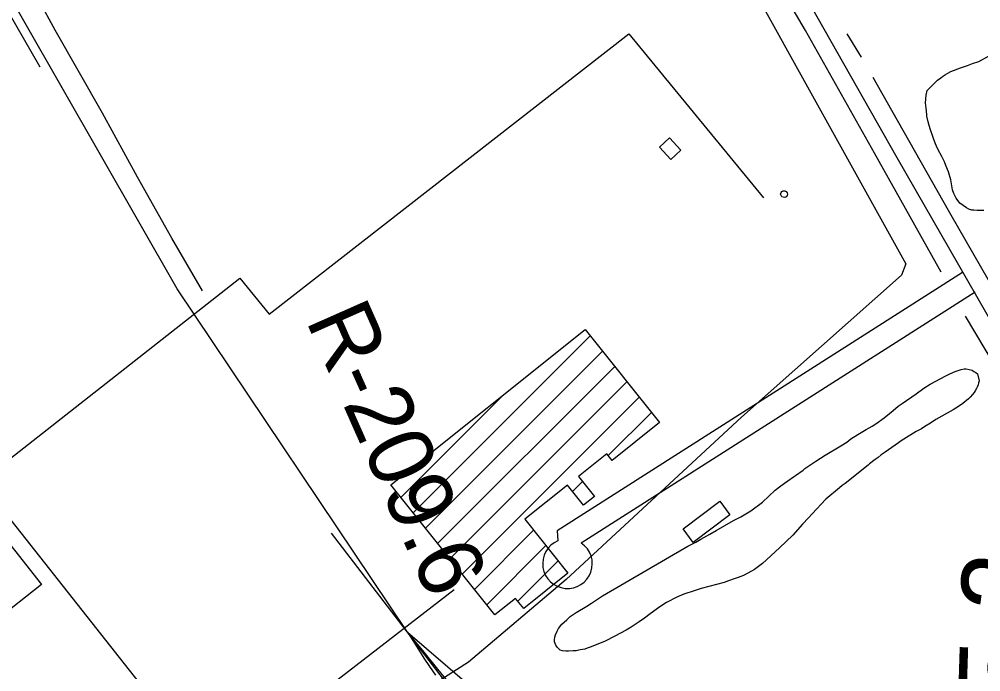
# Model space of a CAD drawing. Extents: x 3297753 to 3335611, y 652252 to 677623.
# Drawn here: x 3314328 to 3315560, y 661323 to 662159 of the extents above; entities that cross this region are included whole.
import ezdxf

# ---------------------------------------------------------------- set-up
doc = ezdxf.new("R2010")
doc.units = 0
for name, color, linetype in [('V-BLDG-OTLN', 7, 'Continuous'), ('V-DOMW-TANK', 7, 'Continuous'), ('V-RAIL-TRAK', 7, 'Continuous'), ('V-RIVR-EDGE', 7, 'Continuous'), ('V-RIVR-RANG-IDEN', 7, 'Continuous'), ('V-ROAD-CNTR', 7, 'Continuous'), ('V-SITE-OTLN', 7, 'Continuous'), ('V-SITE-VEGE', 7, 'Continuous'), ('V-SURV-IDEN', 7, 'Continuous'), ('V-TOPO-SHOR', 7, 'Continuous'), ('V-UTIL-LINE', 7, 'Continuous')]:
    doc.layers.add(name, color=color, linetype=linetype)

msp = doc.modelspace()

# ---------------------------------------------------------------- linework, layer by layer
at = {"layer": 'V-BLDG-OTLN'}
for p, q in [((3314832.2, 661526.9), (3315059.1, 661753.7)), ((3314847.9, 661507.2), (3315074.8, 661734.1)), ((3314863.6, 661487.6), (3315090.5, 661714.4)), ((3314879.3, 661467.9), (3315106.2, 661694.8)), ((3314816.5, 661546.5), (3314947.4, 661677.5)), ((3314895, 661448.3), (3315121.9, 661675.1)), ((3315082.3, 661600.2), (3315137.6, 661655.5)), ((3315036.3, 661554.2), (3315049.2, 661567.1)), ((3314910.8, 661428.6), (3314986.5, 661504.4)), ((3314926.5, 661409), (3315002.2, 661484.7)), ((3314966.4, 661413.6), (3315017.9, 661465.1))]:
    msp.add_line(p, q, dxfattribs=at)
for points in [[(3315160.6, 662007.2), (3315175.3, 661991.6), (3315162.6, 661979.6), (3315147.9, 661995.2)], [(3314803.7, 661562.6), (3315052.8, 661761.6), (3315148.1, 661642.4), (3315087.4, 661593.9), (3315080.6, 661602.5), (3315044.1, 661573.3), (3315064.5, 661547.9), (3315050.4, 661536.6), (3315029.9, 661562.2), (3314975.2, 661518.5), (3315030.5, 661449.4), (3314973.9, 661404.2), (3314963.5, 661417.1), (3314936.8, 661396)], [(3315178.1, 661506.3), (3315225.1, 661541.5), (3315238.1, 661524.1), (3315191.1, 661488.9)], [(3314167.4, 661429.1), (3314286.4, 661522.9), (3314355.9, 661434.8), (3314237, 661341)]]:
    msp.add_lwpolyline(points, close=True, dxfattribs=at)
at = {"layer": 'V-DOMW-TANK'}
msp.add_lwpolyline([(3315311.8, 661935.2), (3315311.4, 661933.5), (3315310.2, 661931.9), (3315308.3, 661931), (3315306.3, 661931.1), (3315304.8, 661931.8), (3315303.6, 661933.2), (3315303.1, 661935.2), (3315303.6, 661937.3), (3315304.8, 661938.7), (3315306.3, 661939.4), (3315308.3, 661939.5), (3315310.2, 661938.6), (3315311.4, 661937)], close=True, dxfattribs=at)
at = {"layer": 'V-RAIL-TRAK'}
for points in [[(3314883.7, 661302.6), (3314864, 661326.4), (3314844.6, 661350.3), (3314825.2, 661374), (3314530.1, 661813.9), (3314234.9, 662329.3)], [(3314825.2, 661374), (3314832, 661363.1), (3314839, 661351.8), (3314846.1, 661340.7), (3314853.3, 661329.7), (3314860.8, 661318.8)], [(3314825.2, 661374), (3314901.1, 661308.4), (3314941.6, 661279), (3314978.9, 661251.9), (3314988.1, 661243.5), (3314997.1, 661234.9), (3315006, 661226.2), (3315014.7, 661217.3), (3315023.2, 661208.2), (3315031.6, 661199), (3315039.8, 661189.7), (3315047.9, 661180.2), (3315175.9, 661016.4)]]:
    msp.add_lwpolyline(points, dxfattribs=at)
at = {"layer": 'V-RIVR-EDGE'}
msp.add_spline([(3319472.9, 662096.8), (3319451.4, 662084.8), (3319431.4, 662073.3), (3319412.8, 662065.4), (3319386.6, 662059.7), (3319355.1, 662056.1), (3319321.5, 662047.4), (3319286.7, 662035.9), (3319261.8, 662024.4), (3319253.9, 662022.3), (3319244, 662022.3), (3319236.9, 662020.3), (3319220.3, 662007.1), (3319214.1, 661999.2), (3319197.9, 661992.6), (3319174.7, 661985.2), (3319135.2, 661974.5), (3319095.8, 661962.6), (3319061.8, 661950.7), (3319035.7, 661940.8), (3319017, 661932.5), (3319004.2, 661925.1), (3318977.6, 661914.4), (3318949.4, 661908.7), (3318929.1, 661903.3), (3318893.4, 661894.3), (3318836.2, 661878.7), (3318802.2, 661869.7), (3318784.3, 661864.3), (3318761.1, 661859.4), (3318735.4, 661848.3), (3318707.2, 661836.3), (3318683.9, 661831.8), (3318667.8, 661829.8), (3318647.9, 661824.9), (3318612.2, 661812.5), (3318583.6, 661801.4), (3318550.8, 661789.5), (3318517.2, 661780.8), (3318486.9, 661770.5), (3318459.1, 661757.8), (3318437.1, 661748.7), (3318401.1, 661732.6), (3318376.3, 661719.7), (3318350.3, 661712.4), (3318322.7, 661702.9), (3318295.6, 661690.6), (3318275.9, 661686.7), (3318257.8, 661681.1), (3318243.7, 661673.2), (3318214.4, 661661.5), (3318180.6, 661645.8), (3318148.4, 661630.1), (3318131.5, 661619.4), (3318111.1, 661604.8), (3318079.5, 661575), (3318056.4, 661560.4), (3318032.7, 661542.4), (3318016.3, 661532.3), (3317961.5, 661489.7), (3317862.7, 661415.5), (3317830, 661391.9), (3317829.4, 661388.6), (3317827.2, 661382.9), (3317810.8, 661375.6), (3317786, 661359.9), (3317761.1, 661342.5), (3317743.6, 661322.8), (3317726.1, 661300.9), (3317708.6, 661279), (3317696.7, 661270.6), (3317673.6, 661255.4), (3317601.3, 661201.5), (3317560.7, 661171.7), (3317529.1, 661153.2), (3317513.8, 661140.3), (3317483.9, 661117.2), (3317464.2, 661105.5), (3317423.5, 661083), (3317409.4, 661079.1), (3317401.5, 661079.1), (3317375, 661065.7), (3317364.3, 661058.9), (3317348.5, 661051.1), (3317330.5, 661046.6), (3317307.3, 661033.2), (3317289.3, 661024.8), (3317263.9, 661012.4), (3317240.8, 661008.5), (3317230.1, 661004), (3317228.4, 661000.1), (3317221.6, 660998.4), (3317196.2, 660991.2), (3317170.3, 660981.7), (3317149.4, 660978.3), (3317103.2, 660961), (3317073.3, 660949.8), (3317034.3, 660929.6), (3316996, 660910), (3316948, 660887), (3316914.7, 660873.5), (3316886, 660860.6), (3316880.9, 660856.2), (3316871.3, 660848.3), (3316865.7, 660846.6), (3316855.5, 660846.6), (3316850.4, 660846.6), (3316844.2, 660840.5), (3316839.7, 660839.9), (3316835.8, 660840.5), (3316830.7, 660836.6), (3316818.8, 660828.7), (3316813.8, 660828.1), (3316808.1, 660827), (3316803.6, 660827), (3316796.8, 660818.6), (3316785, 660809.6), (3316774.8, 660802.9), (3316771.4, 660796.1), (3316765.2, 660779.2), (3316755.6, 660759.5), (3316745.9, 660744.3), (3316732.4, 660728.6), (3316712.6, 660717.9), (3316683.9, 660703.4), (3316676.5, 660701.1), (3316664.7, 660695.5), (3316651.7, 660680.3), (3316633, 660666.9), (3316616.1, 660656.2), (3316590.1, 660637.1), (3316544.4, 660603.4), (3316510, 660581), (3316472.7, 660551.7), (3316428.7, 660523.1), (3316390.3, 660495.6), (3316363.8, 660477.6), (3316349.7, 660469.8), (3316341.2, 660464.7), (3316335, 660464.7), (3316325.4, 660464.8), (3316313.6, 660461.4), (3316289.9, 660457), (3316257.2, 660443.5), (3316237.5, 660436.3), (3316207, 660423.9), (3316177.1, 660405.4), (3316154.5, 660393.1), (3316131.9, 660375.1), (3316110.5, 660362.2), (3316095.3, 660353.2), (3316080, 660338), (3316051.2, 660312.7), (3316013.9, 660270.6), (3315988.5, 660245.8), (3315960.3, 660217.2), (3315939.9, 660200.9), (3315925.8, 660185.1), (3315911.1, 660173.9), (3315895.3, 660159.9), (3315882.9, 660145.8), (3315867.6, 660130.1), (3315849, 660120), (3315837.7, 660109.3), (3315808.9, 660080.1), (3315786.9, 660062.1), (3315758.1, 660038.5), (3315733.8, 660018.8), (3315725.3, 660002.5), (3315692, 659976.7), (3315659.8, 659949.1), (3315603.4, 659904.2), (3315571.2, 659873.3), (3315569.5, 659873.3), (3315558.8, 659868.8), (3315547.5, 659863.2), (3315527.7, 659844.1), (3315506.3, 659828.4), (3315477.5, 659812.1), (3315461.1, 659805.9), (3315440.8, 659793.6), (3315429.5, 659781.8), (3315402.4, 659758.2), (3315361.8, 659731.8), (3315304.2, 659696.4), (3315255.7, 659666.7), (3315169.9, 659624.7), (3315140, 659611.8), (3315123.7, 659603.4), (3315098.8, 659588.8), (3315044.6, 659551.1), (3314989.9, 659507.3), (3314954.3, 659474.7), (3314934, 659462.4), (3314926.1, 659452.8), (3314915.9, 659440.5), (3314897.8, 659423.6), (3314866.8, 659396.1), (3314844.7, 659376.4), (3314848.7, 659370.7), (3314825, 659355), (3314801.8, 659342.7), (3314762.3, 659320.8), (3314730.2, 659303.4), (3314711, 659290.5), (3314664.7, 659256.3), (3314628.6, 659235.5), (3314603.2, 659218.1), (3314584.5, 659209.7), (3314564.8, 659208), (3314555.8, 659204.7), (3314546.8, 659196.2), (3314528.1, 659174.9), (3314492.5, 659118.6), (3314473.8, 659095), (3314450.7, 659074.8), (3314428.7, 659060.2), (3314423, 659054.6), (3314416.2, 659044.4), (3314398.1, 659027.6), (3314375.6, 659007.9), (3314366.5, 659005.1), (3314353.6, 659002.3), (3314347.4, 658997.3), (3314346.8, 658988.8), (3314351.3, 658983.2), (3314350.7, 658974.2), (3314342.8, 658961.8), (3314329.2, 658955.1), (3314311.7, 658940.4), (3314310, 658930.3), (3314294.2, 658921.9), (3314283.5, 658914.6), (3314276.1, 658903.9), (3314272.7, 658896), (3314237.7, 658871.3), (3314206.7, 658853.4), (3314198.2, 658851.1), (3314192, 658850.6), (3314180.2, 658846.1), (3314172.3, 658836.5), (3314164.4, 658823.6), (3314142.3, 658810.1), (3314120.9, 658792.7), (3314097.2, 658778.7), (3314086.5, 658769.1), (3314082.5, 658762.9), (3314080.2, 658754.5), (3314072.3, 658750), (3314036.8, 658734.3), (3314006.3, 658722), (3313997.3, 658716.4), (3313939.7, 658673.7), (3313888.3, 658635), (3313863.5, 658615.3), (3313820.6, 658586.7), (3313772.6, 658558), (3313732, 658532.8), (3313718.5, 658524.4), (3313711.1, 658521.6), (3313702.7, 658521.6), (3313693.1, 658518.8), (3313674.5, 658511.5), (3313646.8, 658494.7), (3313626.5, 658479), (3313619.7, 658475), (3313610.1, 658464.3), (3313605, 658449.1), (3313597.1, 658444.7), (3313577.9, 658428.9), (3313554.8, 658407.6), (3313537.8, 658387.3), (3313525.4, 658364.2), (3313506.1, 658331.6), (3313489.7, 658309.7)], degree=3, dxfattribs=at)
at = {"layer": 'V-ROAD-CNTR'}
for points in [[(3315691.2, 661565.9), (3315452.6, 661981.7), (3315265.5, 662311.8), (3315068.2, 662658.1), (3314991.7, 662786.7), (3314881.6, 662982.8), (3314817.7, 663095.5), (3314653, 663387.7)], [(3315536.1, 661834.9), (3315016.7, 661503.8), (3315017.5, 661490.9)], [(3315552.2, 661809.6), (3315047.7, 661488)], [(3314727.3, 661500.8), (3314914.1, 661256.8), (3315217.7, 660882.3)]]:
    msp.add_lwpolyline(points, dxfattribs=at)
msp.add_arc((3315030, 661461.6), 31.8, 113.0672, 56.0914, dxfattribs=at)
at = {"layer": 'V-SITE-OTLN'}
msp.add_lwpolyline([(3314238.5, 662553.8), (3314592.2, 662807.3), (3314843.4, 662969.8), (3315149.1, 662412.1), (3315463.5, 661846), (3315457.9, 661831.5), (3315253.1, 661649.5), (3315028.5, 661441.3), (3314903.2, 661335.6), (3314820.4, 661282.4), (3315089.4, 660856.8), (3315209.9, 660653.4), (3314859, 660457.6), (3314738.9, 660375), (3314609.1, 660523.7), (3314566.5, 660483.4), (3314505.2, 660440.7), (3314559.6, 660352.4), (3314127.8, 660037.1)], dxfattribs=at)
at = {"layer": 'V-SITE-VEGE'}
for points in [[(3315563.4, 661914), (3315554.8, 661914.1), (3315550.8, 661914.8), (3315548.1, 661914.8), (3315544.2, 661916), (3315541.4, 661917.6), (3315532.8, 661923.5), (3315528.1, 661929.8), (3315525, 661936.1), (3315523.4, 661940.8), (3315521.9, 661948.3), (3315521.1, 661953.4), (3315518, 661963.6), (3315514.8, 661971.8), (3315512.9, 661976.5), (3315509.7, 661983.2), (3315505, 661991.9), (3315502.7, 661996.6), (3315501.5, 661999.7), (3315499.2, 662005.2), (3315498, 662008.8), (3315494.9, 662017.4), (3315493.3, 662022.9), (3315492.1, 662027.6), (3315490.6, 662035.1), (3315490.6, 662037.4), (3315489.4, 662045.3), (3315488.6, 662052.3), (3315489.4, 662061.8), (3315491, 662068), (3315504, 662081), (3315508.3, 662084.1), (3315510.3, 662086.1), (3315514.2, 662088.4), (3315517.4, 662090), (3315521.3, 662092.3), (3315533.5, 662097), (3315542.5, 662100.2), (3315548.8, 662102.5), (3315557, 662105.2), (3315569.6, 662111.9)], [(3315555.4, 661704.8), (3315557.5, 661696), (3315556.6, 661693.4), (3315556, 661690.8), (3315555, 661687.9), (3315554.1, 661685.9), (3315552.2, 661683.3), (3315551.2, 661681), (3315549, 661678.4), (3315545.8, 661675.1), (3315543.9, 661672.8), (3315536.5, 661666.8), (3315531.1, 661663.2), (3315524.3, 661658.8), (3315501.8, 661646.2), (3315495, 661641.8), (3315488, 661637.5), (3315483.5, 661634.5), (3315476.7, 661630.9), (3315457.4, 661619.2), (3315454.2, 661616.6), (3315437.2, 661604.6), (3315431.7, 661601), (3315427.9, 661597.7), (3315424, 661595), (3315417, 661589.4), (3315415.4, 661587.7), (3315415.1, 661588), (3315385.9, 661564.2), (3315382, 661561.6), (3315378.5, 661558.9), (3315361.2, 661544.1), (3315343.3, 661525.6), (3315338.9, 661520.3), (3315331.2, 661512.1), (3315318.8, 661498.3), (3315301.8, 661481.8), (3315279.7, 661461.7), (3315274.6, 661458), (3315269.5, 661454), (3315261.1, 661449.4), (3315255.6, 661446.4), (3315248.5, 661443.7), (3315243.7, 661442), (3315236.3, 661439.6), (3315230.8, 661437.5), (3315221.1, 661434.8), (3315201.4, 661429.6), (3315192.3, 661426.9), (3315179.1, 661422.5), (3315170, 661418.8), (3315156.9, 661411.7), (3315148.2, 661406.1), (3315136, 661397.5), (3315128.6, 661391.8), (3315121.9, 661386.9), (3315111.6, 661380.2), (3315105.1, 661376.5), (3315090.7, 661368.5), (3315078.1, 661362.5), (3315060.4, 661355.1), (3315055.2, 661353.4), (3315052.3, 661352), (3315046.1, 661351), (3315041, 661349.9), (3315037.4, 661349.9), (3315031.2, 661349.4), (3315027.7, 661349.4), (3315023.8, 661350), (3315020.5, 661350.9), (3315016.6, 661354.7), (3315014.9, 661357.3), (3315013.2, 661361.5), (3315013.2, 661364.1), (3315013.8, 661367.3), (3315014.7, 661370.3), (3315016.6, 661375.2), (3315018.5, 661378.5), (3315022.9, 661384), (3315029, 661389.7), (3315033.5, 661393.9), (3315041.2, 661398.9), (3315055, 661407.3), (3315060.8, 661410.9), (3315074.9, 661420.2), (3315184.3, 661484.2), (3315194.3, 661489.2), (3315201, 661493.2), (3315212.3, 661499.6), (3315220.3, 661504.2), (3315242.9, 661516.9), (3315251.9, 661521.6), (3315264.7, 661529.3), (3315279.8, 661540.5), (3315296.1, 661555.7), (3315301.6, 661560), (3315308, 661564.7), (3315312.5, 661567.6), (3315319.6, 661572.9), (3315322.1, 661574.6), (3315331.8, 661581.6)], [(3315331.8, 661581.6), (3315334.3, 661583.6), (3315348.1, 661592.9), (3315360.3, 661600.8), (3315380.3, 661612.5), (3315387.7, 661617.5), (3315393.1, 661621.5), (3315401.8, 661627.1), (3315412.7, 661633.4), (3315420.5, 661637.8), (3315425, 661640.8), (3315435.9, 661648.7), (3315442.6, 661654), (3315447.1, 661657.7), (3315453.5, 661663.6), (3315458.6, 661666.9), (3315476.6, 661679.2), (3315486.6, 661686.5), (3315494.6, 661691.8), (3315514.9, 661702.5), (3315519.7, 661704.9), (3315526.5, 661707.9), (3315534.5, 661710.6), (3315538.1, 661711.3), (3315541, 661711.4), (3315548.5, 661709.5), (3315550.8, 661707.9), (3315553.1, 661706.7), (3315555.4, 661704.8)]]:
    msp.add_lwpolyline(points, dxfattribs=at)
at = {"layer": 'V-TOPO-SHOR'}
msp.add_line((3315406.8, 662110.6), (3315388.4, 662140.7), dxfattribs=at)
for points in [[(3314562.5, 661811.4), (3314523, 661878.7), (3314479.2, 661957), (3314434.1, 662039), (3314373.8, 662145.2), (3314310.8, 662261.2), (3314262.3, 662338.1), (3314224.2, 662404.2), (3314196.5, 662451), (3314175.8, 662479.8), (3314164.6, 662494.8), (3314162.7, 662505.8), (3314164.7, 662515.1), (3314158.3, 662528.8)], [(3314354.4, 662097.7), (3314313.2, 662169.3), (3314278.7, 662233.3), (3314250, 662278), (3314228.7, 662307.3), (3314209.8, 662330.2), (3314189.6, 662350.1), (3314163.7, 662372.6), (3314142.4, 662388.1)], [(3315508.9, 661835), (3315423.3, 661987.5), (3315334.9, 662144.9), (3315307.6, 662192)], [(3315625.4, 661728.5), (3315570.5, 661822.8), (3315519.9, 661911.1), (3315445.5, 662042.2), (3315421.6, 662084.6)], [(3315679.1, 661540.4), (3315591.5, 661692.2), (3315539.8, 661778.8)]]:
    msp.add_lwpolyline(points, dxfattribs=at)
at = {"layer": 'V-UTIL-LINE'}
for p, q in [((3314575.9, 661189.8), (3314278, 661566.7)), ((3314374.7, 661034.1), (3314884.7, 661428.7))]:
    msp.add_line(p, q, dxfattribs=at)
msp.add_lwpolyline([(3313986.5, 661337.8), (3314610.2, 661827.6), (3314647.9, 661781.5), (3315108.4, 662140.6), (3315281.2, 661930.3)], dxfattribs=at)

# ---------------------------------------------------------------- texts
at = {"layer": 'V-RIVR-RANG-IDEN'}
msp.add_text('R-209.6', height=83, rotation=293.8812, dxfattribs=at).set_placement((3314694.1, 661773.9))
at = {"layer": 'V-SURV-IDEN'}
msp.add_text('4382+85.2', height=100, rotation=88.2067, dxfattribs=at).set_placement((3315616.4, 660838.5))

doc.saveas('drawing.dxf')
